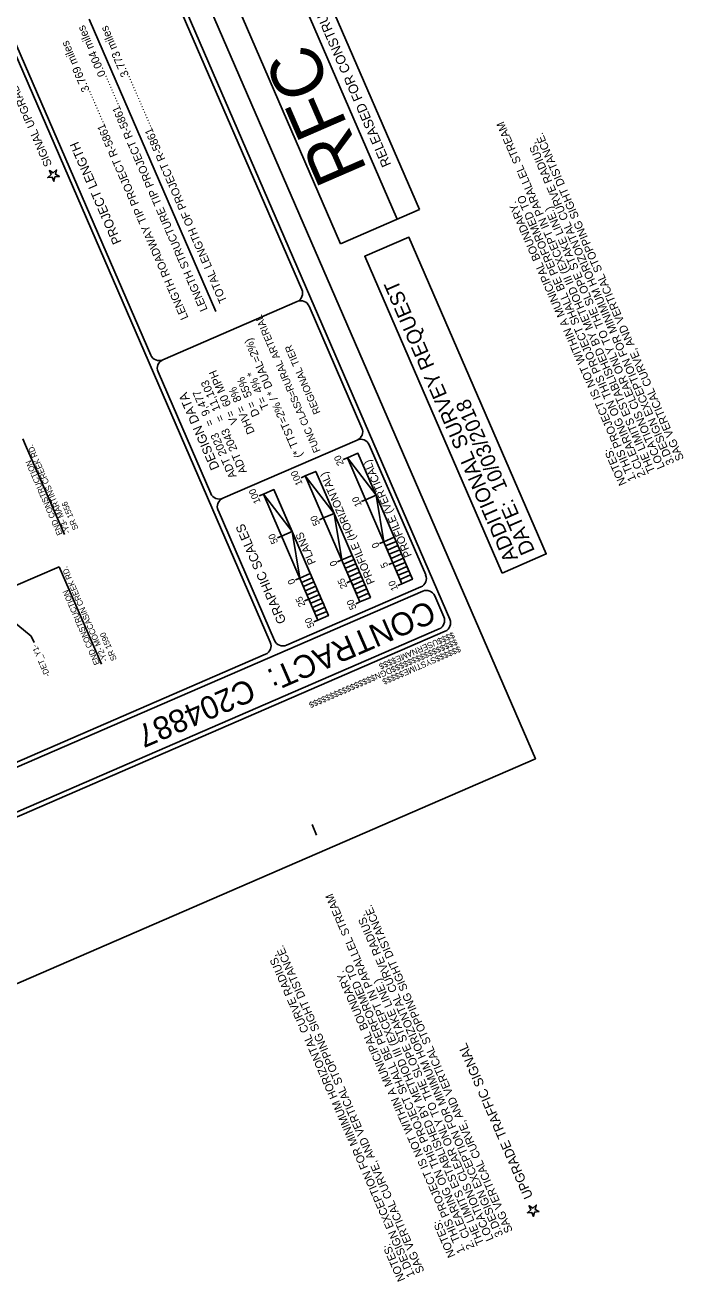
# Model space of a CAD drawing. Extents: x 442728 to 492797, y 479541 to 511293.
# Drawn here: x 482000 to 492797, y 479541 to 500146 of the extents above; entities that cross this region are included whole.
import ezdxf

# ---------------------------------------------------------------- set-up
doc = ezdxf.new("R2010")
doc.units = 0
for name, color, linetype in [('Old_Level_5', 7, 'Continuous'), ('Prop DSN Text', 7, 'Continuous'), ('Prop PHM Text', 7, 'Continuous'), ('Prop RDY Traffic Signal CELL', 7, 'Continuous'), ('Sheet Data Field CELL', 7, 'Continuous'), ('Sheet Plot Border Outside CELL', 7, 'Continuous'), ('Sheet Title CELL', 7, 'Continuous')]:
    doc.layers.add(name, color=color, linetype=linetype)

msp = doc.modelspace()

# ---------------------------------------------------------------- linework, layer by layer
at = {"layer": 'Old_Level_5'}
for p, q in [((486518, 501610), (488464, 497123)), ((486155, 501452), (488100, 496965)), ((487172, 496562), (485226, 501050)), ((488464, 497123), (487172, 496562))]:
    msp.add_line(p, q, dxfattribs=at)
at = {"layer": 'Prop DSN Text'}
for p, q in [((482009, 493258), (481963, 493363)), ((482644, 491794), (482007, 493261)), ((482559, 491265), (481846, 490956)), ((483251, 489667), (482559, 491265)), ((482101, 490127), (481270, 490810)), ((482147, 490022), (482101, 490127))]:
    msp.add_line(p, q, dxfattribs=at)
at = {"layer": 'Prop PHM Text'}
msp.add_lwpolyline([(489820, 491162), (487568, 496356), (488290, 496669), (490542, 491475)], close=True, dxfattribs=at)
at = {"layer": 'Prop RDY Traffic Signal CELL'}
for points in [[(482445, 497654), (482473, 497587), (482489, 497658), (482562, 497665), (482499, 497702), (482515, 497773), (482460, 497725), (482398, 497762), (482427, 497695), (482372, 497647), (482445, 497654)], [(490306, 480681), (490335, 480614), (490351, 480685), (490423, 480692), (490361, 480729), (490377, 480800), (490322, 480752), (490260, 480788), (490289, 480722), (490234, 480674), (490306, 480681)]]:
    msp.add_lwpolyline(points, dxfattribs=at)
at = {"layer": 'Sheet Data Field CELL'}
for p, q in [((485124, 495453), (483048, 500241)), ((485905, 492456), (485836, 492426)), ((486203, 491767), (486135, 491738)), ((486651, 490735), (486582, 490705)), ((486800, 490391), (486732, 490361)), ((489022, 490267), (489022, 490267))]:
    msp.add_line(p, q, dxfattribs=at)
at = {"layer": 'Sheet Plot Border Outside CELL'}
msp.add_lwpolyline([(465175, 504729), (475225, 481554), (490363, 488118), (480314, 511293)], close=True, dxfattribs=at)
at = {"layer": 'Sheet Title CELL'}
for p, q in [((486019, 490028), (477546, 509570)), ((484060, 494737), (481792, 499967)), ((484257, 494659), (486459, 495614)), ((485044, 492466), (484179, 494462)), ((485241, 492388), (487443, 493343)), ((487454, 493127), (487282, 493052)), ((488349, 491062), (487454, 493127)), ((487282, 493052), (487213, 493022)), ((487282, 493052), (487213, 493022)), ((487282, 493052), (487213, 493022)), ((487282, 493052), (488177, 490988)), ((487282, 493052), (488177, 490988)), ((487282, 493052), (488177, 490988)), ((486593, 492754), (486525, 492724)), ((486593, 492754), (486525, 492724)), ((486765, 492828), (486593, 492754)), ((486593, 492754), (487489, 490690)), ((486593, 492754), (487489, 490690)), ((487661, 490764), (486765, 492828)), ((485905, 492455), (485837, 492426)), ((486078, 492530), (485905, 492455)), ((485905, 492455), (486800, 490391)), ((486972, 490466), (486078, 492530)), ((487580, 492364), (487511, 492334)), ((487580, 492364), (487511, 492334)), ((487580, 492364), (487511, 492334)), ((487580, 492364), (487752, 492439)), ((486088, 490058), (485163, 492191)), ((486892, 492066), (486823, 492036)), ((486892, 492066), (486823, 492036)), ((486892, 492066), (487064, 492140)), ((486204, 491767), (486376, 491842)), ((486204, 491767), (486135, 491738)), ((487878, 491676), (487810, 491646)), ((487878, 491676), (487810, 491646)), ((487878, 491676), (487810, 491646)), ((487968, 491470), (488140, 491544)), ((487190, 491378), (487122, 491348)), ((487190, 491378), (487122, 491348)), ((487280, 491171), (487452, 491246)), ((488027, 491332), (487959, 491302)), ((488027, 491332), (487959, 491302)), ((488027, 491332), (487959, 491302)), ((486502, 491079), (486433, 491049)), ((487339, 491034), (487271, 491004)), ((487339, 491034), (487271, 491004)), ((488177, 490988), (488349, 491062)), ((488517, 490866), (474480, 484779)), ((488488, 490935), (486286, 489980)), ((486592, 490873), (486764, 490947)), ((488177, 490988), (488108, 490958)), ((488177, 490988), (488108, 490958)), ((488177, 490988), (488108, 490958)), ((488108, 490958), (488108, 490958)), ((488177, 490988), (488177, 490988)), ((488177, 490988), (488177, 490988)), ((488177, 490988), (488177, 490988)), ((486651, 490735), (486582, 490705)), ((487489, 490690), (487420, 490660)), ((487489, 490690), (487420, 490660)), ((487420, 490660), (487420, 490660)), ((487489, 490690), (487661, 490764)), ((487489, 490690), (487489, 490690)), ((487489, 490690), (487489, 490690)), ((486800, 490391), (486732, 490361)), ((486800, 490391), (486972, 490466)), ((486800, 490391), (486800, 490391)), ((486732, 490361), (486732, 490361)), ((489022, 490267), (489022, 490267)), ((489022, 490267), (489022, 490267)), ((489022, 490267), (489022, 490267)), ((489022, 490267), (489022, 490267)), ((485942, 489831), (474450, 484848)), ((486778, 486866), (486703, 487038)), ((486778, 486866), (486703, 487038))]:
    msp.add_line(p, q, dxfattribs=at)
for points in [[(488963, 490405), (480131, 510773)], [(486537, 495811), (484269, 501041)], [(487521, 493540), (486656, 495536)], [(488566, 491132), (487640, 493265)], [(488864, 490444), (488715, 490788)], [(474710, 484061), (488885, 490208)], [(474710, 484061), (488885, 490208)], [(474749, 484160), (488786, 490246)]]:
    msp.add_lwpolyline(points, dxfattribs=at)
for points in [[(487282, 493052), (487752, 492439), (487454, 493127)], [(486593, 492754), (487064, 492140), (486765, 492828)], [(485905, 492455), (486376, 491842), (486078, 492530)], [(487878, 491676), (487752, 492439), (488050, 491751)], [(487190, 491378), (487064, 492140), (487362, 491452)], [(486502, 491079), (486376, 491842), (486674, 491154)], [(487938, 491538), (487908, 491607), (488080, 491682), (488110, 491613)], [(487998, 491401), (487968, 491470), (488140, 491544), (488170, 491475)], [(487250, 491240), (487220, 491309), (487392, 491383), (487422, 491315)], [(487310, 491102), (487280, 491171), (487452, 491246), (487482, 491177)], [(488057, 491263), (488027, 491332), (488200, 491407), (488229, 491338)], [(488117, 491125), (488087, 491194), (488259, 491269), (488289, 491200)], [(486562, 490942), (486532, 491010), (486704, 491085), (486734, 491016)], [(487369, 490965), (487339, 491034), (487511, 491108), (487541, 491039)], [(488177, 490988), (488147, 491057), (488319, 491131), (488349, 491062)], [(486622, 490804), (486592, 490873), (486764, 490947), (486793, 490879)], [(486681, 490666), (486651, 490735), (486823, 490810), (486853, 490741)], [(487429, 490827), (487399, 490896), (487571, 490971), (487601, 490902)], [(487489, 490690), (487459, 490758), (487631, 490833), (487661, 490764)], [(486741, 490529), (486711, 490598), (486883, 490672), (486913, 490604)], [(486800, 490391), (486771, 490460), (486943, 490534), (486972, 490466)]]:
    msp.add_lwpolyline(points, close=True, dxfattribs=at)
for centre, start, end in [((486398, 495751), 293.4424, 23.4424), ((486518, 495476), 23.4424, 113.4424), ((484196, 494796), 203.4424, 293.4424), ((484316, 494521), 113.4424, 203.4424), ((487383, 493480), 293.4424, 23.4424), ((487502, 493205), 23.4424, 113.4424), ((485181, 492526), 203.4424, 293.4424), ((485300, 492250), 113.4424, 203.4424), ((488427, 491072), 293.4424, 23.4424), ((488576, 490728), 23.4424, 113.4424), ((488726, 490384), 293.4424, 23.4424), ((488824, 490345), 293.4424, 23.4424), ((485881, 489968), 293.4424, 23.4424), ((486225, 490117), 203.4424, 293.4424)]:
    msp.add_arc(centre, 150, start, end, dxfattribs=at)

# ---------------------------------------------------------------- texts
at = {"layer": 'Old_Level_5'}
for s, height, p in [('RELEASED FOR CONSTRUCTION', 156.65, (488003, 497861)), ('RFC', 843.5, (487615, 497767))]:
    msp.add_text(s, height=height, rotation=113.4416, dxfattribs=at).set_placement(p)
at = {"layer": 'Prop DSN Text'}
for s, height, p in [('-Y3- MARTINS CREEK RD.', 94.92, (482746, 491836)), ('END CONSTRUCTION', 94.92, (482617, 491805)), ('SR 1556', 94.9, (482877, 491892)), ('-Y2- MOCCASIN CREEK RD.', 94.92, (483355, 489735)), ('END CONSTRUCTION', 94.92, (483225, 489679)), ('SR 1590', 94.9, (483505, 489748)), ('-DET_Y1- ', 94.9, (482413, 489486)), ('UPGRADE TRAFFIC SIGNAL', 154, (490328, 480942))]:
    msp.add_text(s, height=height, rotation=113.4424, dxfattribs=at).set_placement(p)
at = {"layer": 'Prop PHM Text'}
for s, p in [('ADDITIONAL SURVEY REQUEST', (490083, 491406)), ('DATE:  10/03/2018', (490360, 491525))]:
    msp.add_text(s, height=241, rotation=113.4406, dxfattribs=at).set_placement(p)
at = {"layer": 'Sheet Data Field CELL'}
for s, height, p in [('LENGTH STRUCTURE TIP PROJECT R-5861...........0.004 miles', 131.25, (484995, 495485)), ('TOTAL LENGTH OF PROJECT R-5861...................3.773 miles', 131.25, (485311, 495622)), ('LENGTH ROADWAY TIP PROJECT R-5861............3.769 miles', 131.25, (484679, 495349)), ('SIGNAL UPGRADE', 131.25, (482443, 497860)), ('THE LIMITS ESTABLISHED BY METHOD III (EXCEPT IN PARALLEL STREAM', 131.25, (492332, 492833)), ('3.DESIGN EXCEPTION FOR MINIMUM HORIZONTAL CURVE RADIUS,', 131.25, (492645, 492969)), ('SAG VERTICAL CURVE, AND VERTICAL STOPPING SIGHT DISTANCE. ', 131.25, (492802, 493037)), ('1.THIS PROJECT IS NOT WITHIN A MUNICIPAL BOUNDARY.', 131.25, (492019, 492698)), ('2.CLEARING ON THIS PROJECT SHALL BE PERFORMED TO ', 131.25, (492176, 492765)), ('LOCATIONS CLEAR ONLY TO THE SLOPE STAKE LINE.) ', 131.25, (492489, 492901)), ('FUNC CLASS=RURAL ARTERIAL', 118.13, (486845, 493166)), ('(* TTST=2% / * DUAL=2%)', 131.25, (486549, 493085)), ('REGIONAL TIER', 118.13, (486845, 493796)), ('11,103', 131.3, (485208, 493846)), ('60 MPH', 131.3, (485380, 493921)), ('55%', 131.3, (485724, 494070)), ('4% *', 131.3, (485896, 494144)), ('9,477', 131.3, (485036, 493771)), ('8%', 131.3, (485552, 493995)), ('=', 131, (485615, 493825)), ('=', 131, (485787, 493899)), ('=', 131, (485959, 493974)), ('T', 131, (486002, 493874)), ('=', 131, (485271, 493676)), ('=', 131, (485443, 493750)), ('V', 131, (485494, 493633)), ('DHV', 131.3, (485767, 493473)), ('D', 131, (485848, 493758)), ('=', 131, (485099, 493601)), (' ADT 2043', 131.3, (485660, 492778)), (' ADT 2023', 131.3, (485488, 492704)), ('20', 112.5, (487227, 492952)), ('NOTES:', 131.3, (491862, 492630)), ('100', 112.5, (486551, 492625)), ('100', 112.5, (485863, 492327)), ('10', 112.5, (487520, 492276)), ('50', 112.5, (486837, 491966)), ('50', 112.5, (486149, 491667)), ('5', 113, (487954, 491275)), ('25', 112.5, (487284, 490935)), ('10', 112.5, (488116, 490900)), ('25', 112.5, (486596, 490637)), ('50', 112.5, (487434, 490589)), ('50', 112.5, (486746, 490291)), ('THE LIMITS ESTABLISHED BY METHOD III (EXCEPT IN PARALLEL STREAM', 131.25, (489527, 480175)), ('SAG VERTICAL CURVE, AND VERTICAL STOPPING SIGHT DISTANCE. ', 131.25, (489996, 480378)), ('3.DESIGN EXCEPTION FOR MINIMUM HORIZONTAL CURVE RADIUS,', 131.25, (489840, 480310)), ('SAG VERTICAL CURVE, AND VERTICAL STOPPING SIGHT DISTANCE. ', 131.25, (488548, 479716)), ('1.DESIGN EXCEPTION FOR MINIMUM HORIZONTAL CURVE RADIUS,', 131.25, (488392, 479648)), ('1. THIS PROJECT IS NOT WITHIN A MUNICIPAL BOUNDARY.', 131.25, (489214, 480039)), ('2. CLEARING ON THIS PROJECT SHALL BE PERFORMED TO ', 131.25, (489370, 480107)), ('LOCATIONS CLEAR ONLY TO THE SLOPE STAKE LINE.)', 131.25, (489683, 480243)), ('NOTES:', 131.3, (489057, 479971)), ('NOTES:', 131.3, (488235, 479580))]:
    msp.add_text(s, height=height, rotation=113.4424, dxfattribs=at).set_placement(p)
at = {"layer": 'Sheet Title CELL'}
for s, height, rotation, p in [('PROJECT LENGTH', 150, 113.4424, (483584, 496592)), ('DESIGN DATA', 150, 113.4424, (485189, 492891)), ('PROFILE (VERTICAL)', 127.5, 113.4424, (488342, 491451)), ('PROFILE (HORIZONTAL)', 127.5, 113.4424, (487736, 491010)), ('GRAPHIC SCALES', 150, 113.4424, (486284, 490368)), ('PLANS', 127.5, 113.4424, (486768, 491333)), ('0', 113, 113.4424, (487810, 491601)), ('0', 113, 113.4424, (487812, 491602)), ('0', 113, 113.4424, (487812, 491602)), ('0', 113, 113.4424, (487122, 491303)), ('0', 113, 113.4424, (487124, 491304)), ('0', 113, 113.4424, (486434, 491005)), ('CONTRACT:', 375, 203.4424, (488620, 490724)), ('$$$$USERNAME$$$$', 98.44, 203.4424, (489014, 490198)), ('$$$$$$$$$$$$$$$$DGN$$$$$$$$$$$$$$$$', 98.44, 203.4424, (489060, 490084)), ('$$$$$$SYSTIME$$$$$', 98.44, 203.4424, (489115, 489969)), ('C204887', 375, 203.4424, (485665, 489443))]:
    msp.add_text(s, height=height, rotation=rotation, dxfattribs=at).set_placement(p)

doc.saveas('drawing.dxf')
